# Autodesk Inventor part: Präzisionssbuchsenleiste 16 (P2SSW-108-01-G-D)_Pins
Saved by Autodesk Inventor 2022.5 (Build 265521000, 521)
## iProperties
Created: 2024-12
Part Number: Präzisionssbuchsenleiste 16 (P2SSW-108-01-G-D)_Pins
Material: Generic
Document SubType Name: Modeling
Designer: AdminForWorker
Density: 1 g/cm^3
Appearance: Default
Title: Präzisionssbuchsenleiste 16 (P2SSW-108-01-G-D)_Pins
Author: AdminForWorker
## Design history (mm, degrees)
feature "Body1"
body "Solid1"
